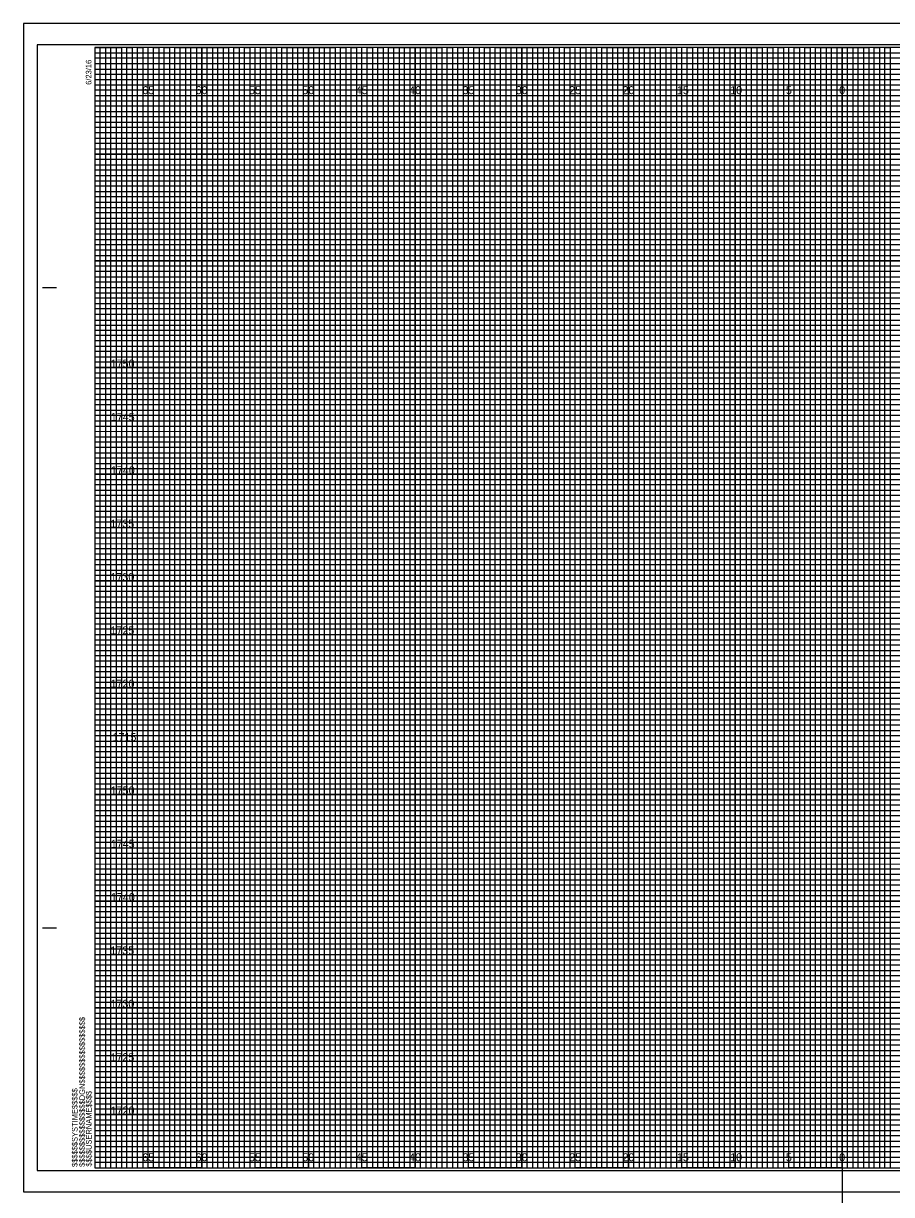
# Model space of a CAD drawing. Extents: x -7 to 162, y -2 to 327.
# Drawn here: x -6.7 to 74.6, y 107.5 to 217.2 of the extents above; entities that cross this region are included whole.
import ezdxf

# ---------------------------------------------------------------- set-up
doc = ezdxf.new("R2010")
doc.units = 0
for name, color, linetype in [('Prop XS Elevation Labels', 7, 'Continuous'), ('Prop XS Offset Labels', 7, 'Continuous'), ('Scratch_Level_5', 7, 'Continuous'), ('Sheet Cross Section CELL', 7, 'Continuous'), ('Sheet Cross Section Grid Major CELL', 7, 'Continuous'), ('Sheet Cross Section Grid Middle CELL', 7, 'Continuous'), ('Sheet Cross Section Grid Minor 1 CELL', 7, 'Continuous'), ('Sheet Cross Section Grid Minor 2 CELL', 7, 'Continuous'), ('Sheet Cutting Line CELL', 7, 'Continuous'), ('Sheet DOT Grid CELL', 7, 'Continuous'), ('Sheet Plot Border Inside CELL', 7, 'Continuous'), ('Sheet Plot Border Outside CELL', 7, 'Continuous')]:
    doc.layers.add(name, color=color, linetype=linetype)

msp = doc.modelspace()

# ---------------------------------------------------------------- linework, layer by layer
at = {"layer": 'Scratch_Level_5'}
msp.add_line((70, 176.62), (70, 106.52), dxfattribs=at)
at = {"layer": 'Sheet Cross Section CELL'}
for p, q in [((-4.9, 192.5), (-3.65, 192.5)), ((-4.85, 192.5), (-3.6, 192.5)), ((-4.9, 132.5), (-3.65, 132.5)), ((-4.85, 132.5), (-3.6, 132.5)), ((0, 110), (0, 110)), ((0, 110), (0, 110)), ((0, 110), (0, 110)), ((0, 110), (0, 110)), ((0, 110), (0, 110)), ((0, 110), (0, 110)), ((0, 110), (0, 110))]:
    msp.add_line(p, q, dxfattribs=at)
msp.add_lwpolyline([(160, 215), (0, 215), (0, 110), (160, 110)], close=True, dxfattribs=at)
at = {"layer": 'Sheet Cross Section Grid Major CELL'}
for p, q in [((5, 215), (0, 215)), ((5, 110), (5, 215)), ((15, 215), (10, 215)), ((10, 215), (10, 110)), ((15, 110), (15, 215)), ((25, 215), (20, 215)), ((20, 215), (20, 110)), ((25, 110), (25, 215)), ((35, 215), (30, 215)), ((30, 215), (30, 110)), ((35, 110), (35, 215)), ((45, 215), (40, 215)), ((40, 215), (40, 110)), ((45, 110), (45, 215)), ((55, 215), (50, 215)), ((50, 215), (50, 110)), ((55, 110), (55, 215)), ((65, 215), (60, 215)), ((60, 215), (60, 110)), ((65, 110), (65, 215)), ((75, 215), (70, 215)), ((70, 215), (70, 110)), ((10, 110), (5, 110)), ((20, 110), (15, 110)), ((30, 110), (25, 110)), ((40, 110), (35, 110)), ((50, 110), (45, 110)), ((60, 110), (55, 110)), ((70, 110), (65, 110))]:
    msp.add_line(p, q, dxfattribs=at)
for points in [[(0, 210), (160, 210), (160, 205), (0, 205)], [(0, 200), (160, 200), (160, 195), (0, 195)], [(0, 190), (160, 190), (160, 185), (0, 185)], [(0, 180), (160, 180), (160, 175), (0, 175)], [(0, 170), (160, 170), (160, 165), (0, 165)], [(0, 160), (160, 160), (160, 155), (0, 155)], [(0, 150), (160, 150), (160, 145), (0, 145)], [(0, 140), (160, 140), (160, 135), (0, 135)], [(0, 130), (160, 130), (160, 125), (0, 125)], [(0, 120), (160, 120), (160, 115), (0, 115)]]:
    msp.add_lwpolyline(points, dxfattribs=at)
at = {"layer": 'Sheet Cross Section Grid Middle CELL'}
for points in [[(0, 215), (2.5, 215), (2.5, 110), (7.5, 110), (7.5, 215), (12.5, 215), (12.5, 110), (17.5, 110), (17.5, 215), (22.5, 215), (22.5, 110), (27.5, 110), (27.5, 215), (32.5, 215), (32.5, 110), (37.5, 110), (37.5, 215), (42.5, 215), (42.5, 110), (47.5, 110), (47.5, 215), (52.5, 215), (52.5, 110), (57.5, 110), (57.5, 215), (62.5, 215), (62.5, 110), (67.5, 110), (67.5, 215), (72.5, 215), (72.5, 110), (77.5, 110)], [(0, 212.5), (137.5, 212.5)], [(0, 202.5), (160, 202.5), (160, 207.5), (0, 207.5)], [(0, 192.5), (160, 192.5), (160, 197.5), (0, 197.5)], [(0, 182.5), (160, 182.5), (160, 187.5), (0, 187.5)], [(0, 172.5), (160, 172.5), (160, 177.5), (0, 177.5)], [(0, 162.5), (160, 162.5), (160, 167.5), (0, 167.5)], [(0, 152.5), (160, 152.5), (160, 157.5), (0, 157.5)], [(0, 142.5), (160, 142.5), (160, 147.5), (0, 147.5)], [(0, 132.5), (160, 132.5), (160, 137.5), (0, 137.5)], [(0, 122.5), (160, 122.5), (160, 127.5), (0, 127.5)], [(0, 112.5), (160, 112.5), (160, 117.5), (0, 117.5)]]:
    msp.add_lwpolyline(points, dxfattribs=at)
at = {"layer": 'Sheet Cross Section Grid Minor 1 CELL'}
for p, q in [((0, 214.5), (130, 214.5)), ((130, 213.99), (0, 213.99)), ((0, 213.99), (0, 213.5)), ((0, 213.5), (130, 213.5)), ((130, 212.94), (0, 212.94)), ((0, 212.94), (0, 212)), ((0, 212), (160, 212))]:
    msp.add_line(p, q, dxfattribs=at)
for points in [[(0, 211.5), (135, 211.5), (160, 211.5), (160, 211), (0, 211)], [(0, 210.5), (160, 210.5), (160, 209.5), (0, 209.5)], [(0, 209), (160, 209), (160, 208.5), (0, 208.49)], [(0, 208), (160, 208), (160, 207), (0, 207)], [(0, 206.5), (160, 206.5), (160, 206), (0, 206)], [(0, 205.5), (160, 205.5), (160, 204.5), (0, 204.5)], [(0, 204), (160, 204), (160, 203.5), (0, 203.5)], [(0, 203), (160, 203), (160, 202), (0, 202)], [(0, 201.5), (160, 201.5), (160, 201), (0, 201)], [(0, 200.5), (160, 200.5), (160, 199.5), (0, 199.5)], [(0, 199), (160, 199), (160, 198.5), (0, 198.5)], [(0, 198), (160, 198), (160, 196.97), (160, 196.5), (160, 196), (0, 196)], [(0, 197), (160, 197), (160, 196.5), (0, 196.5)], [(0, 195.5), (160, 195.5), (160, 194.5), (0, 194.52)], [(0, 194.52), (160, 194.5), (160, 194), (0, 194)], [(0, 193.5), (160, 193.5), (160, 193), (0, 193)], [(0, 192), (160, 192), (160, 191.5), (0, 191.5)], [(0, 191), (160, 191), (160, 190.5), (0, 190.5)], [(-0.04, 189.44), (160, 189.44), (160, 188.94), (-0.04, 188.94)], [(0, 188.5), (160, 188.5), (160, 188), (0, 188)], [(0, 187), (160, 187), (160, 186.5), (0, 186.5)], [(0, 186), (160, 186), (160, 185.5), (0, 185.5)], [(0, 184.5), (160, 184.5), (160, 184), (0, 184)], [(0, 183.5), (160, 183.5), (160, 183), (0, 183)], [(0, 182), (160, 182), (160, 181.5), (0, 181.5)], [(0, 181), (160, 181), (160, 180.5), (0, 180.5)], [(0, 179.5), (160, 179.5), (160, 178.99), (0, 179)], [(0, 178.5), (160, 178.5), (160, 178), (0, 178)], [(0, 177), (160, 177), (160, 176.5), (0, 176.5)], [(0, 176), (160, 176), (160, 175.5), (0, 175.5)], [(0, 174.5), (160, 174.5), (160, 174), (0, 174)], [(0, 173.5), (160, 173.5), (160, 173), (0, 173)], [(0, 172), (160, 172), (160, 171.5), (0, 171.5)], [(0, 171), (160, 171), (160, 170.5), (0, 170.5)], [(0, 169.5), (160, 169.5), (160, 169), (0, 169)], [(0, 168.5), (160.03, 168.46), (160, 168), (0, 168)], [(0, 167), (160, 167), (160, 166.5), (0, 166.5)], [(0, 166), (160, 166), (160, 165.5), (0, 165.5)], [(0, 164.5), (160, 164.5), (160, 164), (0, 164)], [(0, 163.5), (160, 163.5), (160, 163), (0, 163)], [(0, 162), (160, 162), (160, 161.5), (0, 161.5)], [(0, 161), (160, 161), (160, 160.5), (0, 160.5)], [(0, 159.5), (160, 159.5), (160, 159), (0, 159)], [(0, 158.5), (160, 158.5), (160, 158), (0, 158)], [(0, 157), (160, 157), (160, 156.5), (0, 156.5)], [(0, 156), (160, 156), (160, 155.5), (0, 155.5)], [(0, 154.5), (160, 154.5), (160, 154), (0, 154)], [(0, 153.5), (160, 153.5), (160, 153), (0, 153)], [(0, 152), (160, 152), (160, 151.5), (0, 151.5)], [(0, 151), (160, 151), (160, 150.5), (0, 150.5)], [(0, 149.5), (160, 149.5), (160, 148.99), (0, 149)], [(0, 148.5), (160, 148.5), (160, 148), (0, 148)], [(0, 147), (160, 147), (160, 146.5), (0, 146.5)], [(0, 146), (160, 146), (160, 145.5), (0, 145.5)], [(0, 144.5), (160, 144.5), (160, 144), (0, 144)], [(0, 143.5), (160, 143.5), (160, 143), (0, 143)], [(0, 142), (160, 142), (160, 141.5), (0, 141.5)], [(0, 141), (160, 141), (160, 140.5), (0, 140.5)], [(0, 139.5), (160, 139.5), (160, 139), (0, 139)], [(0, 138.5), (160.03, 138.46), (160, 138), (0, 138)], [(0, 137), (160, 137), (160, 136.5), (0, 136.5)], [(0, 136), (160, 136), (160, 135.5), (0, 135.5)], [(0, 134.5), (160, 134.5), (160, 134), (0, 134)], [(0, 133.5), (160, 133.5), (160, 133), (0, 133)], [(0, 132), (160, 132), (160, 131.5), (0, 131.5)], [(0, 131), (160, 131), (160, 130.5), (0, 130.5)], [(0, 129.5), (160, 129.5), (160, 129), (0, 129)], [(0, 128.5), (160, 128.5), (160, 128), (0, 128)], [(0, 127), (160, 127), (160, 126.5), (0, 126.5)], [(0, 126), (160, 126), (160, 125.5), (0, 125.5)], [(0, 124.5), (160, 124.5), (160, 124), (0, 124)], [(0, 123.5), (160, 123.5), (160, 123), (0, 123)], [(0, 122), (160, 122), (160, 121.5), (0, 121.5)], [(0, 121), (160, 121), (160, 120.5), (0, 120.5)], [(0, 119.5), (160, 119.5), (160, 119), (0, 119)], [(0, 118.5), (160, 118.5), (160, 118), (0, 118)], [(0, 117), (160, 117), (160, 116.5), (0, 116.5)], [(0, 116), (160, 116), (160, 115.5), (0, 115.5)], [(0, 114.5), (160, 114.5), (160, 114), (0, 114)], [(0, 113.5), (160, 113.5), (160, 113), (0, 113)], [(0, 112), (160, 112), (160, 111.5), (0, 111.5)], [(0, 111), (160, 111), (160, 110.5), (0, 110.5)]]:
    msp.add_lwpolyline(points, dxfattribs=at)
at = {"layer": 'Sheet Cross Section Grid Minor 2 CELL'}
for points in [[(0, 110), (0.5, 110), (0.5, 215), (1, 215), (1, 110)], [(1, 110), (1.5, 110), (1.5, 215), (2, 215), (2, 110)], [(2.5, 110), (3, 110), (3, 215), (3.5, 215), (3.5, 110)], [(3.5, 110), (4, 110), (4, 215), (4.5, 215), (4.5, 110)], [(5, 110), (5.5, 110), (5.5, 215), (6, 215), (6, 110)], [(6, 110), (6.5, 110), (6.5, 215), (7, 215), (7, 110)], [(7.5, 110), (8, 110), (8, 215), (8.5, 215), (8.5, 110)], [(8.5, 110), (9, 110), (9, 215), (9.5, 215), (9.5, 110)], [(10, 110), (10.5, 110), (10.5, 215), (11, 215), (11, 110)], [(11, 110), (11.5, 110), (11.5, 215), (12, 215), (12, 110)], [(12.5, 110), (13, 110), (13, 215), (13.5, 215), (13.5, 110)], [(13.5, 110), (14, 110), (14, 215), (14.5, 215), (14.5, 110)], [(15, 110), (15.5, 110), (15.5, 215), (16, 215), (16, 110)], [(16, 110), (16.5, 110), (16.5, 215), (17, 215), (17, 110)], [(17.5, 110), (18, 110), (18, 215), (18.5, 215), (18.5, 110)], [(18.5, 110), (19, 110), (19, 215), (19.5, 215), (19.5, 110)], [(20, 110), (20.5, 110), (20.5, 215), (21, 215), (21, 110)], [(21, 110), (21.5, 110), (21.5, 215), (22, 215), (22, 110)], [(22.5, 110), (23, 110), (23, 215), (23.5, 215), (23.5, 110)], [(23.5, 110), (24, 110), (24, 215), (24.5, 215), (24.5, 110)], [(25, 110), (25.5, 110), (25.5, 215), (26, 215), (26, 110)], [(26, 110), (26.5, 110), (26.5, 215), (27, 215), (27, 110)], [(27.5, 110), (28, 110), (28, 215), (28.5, 215), (28.5, 110)], [(28.5, 110), (29, 110), (29, 215), (29.5, 215), (29.5, 110)], [(30, 110), (30.5, 110), (30.5, 215), (31, 215), (31, 110)], [(31, 110), (31.5, 110), (31.5, 215), (32, 215), (32, 110)], [(32.5, 110), (33, 110), (33, 215), (33.5, 215), (33.5, 110)], [(33.5, 110), (34, 110), (34, 215), (34.5, 215), (34.5, 110)], [(35, 110), (35.5, 110), (35.5, 215), (36, 215), (36, 110)], [(36, 110), (36.5, 110), (36.5, 215), (37, 215), (37, 110)], [(37.5, 110), (38, 110), (38, 215), (38.5, 215), (38.5, 110)], [(38.5, 110), (39, 110), (39, 215), (39.5, 215), (39.5, 110)], [(40, 110), (40.5, 110), (40.5, 215), (41, 215), (41, 110)], [(41, 110), (41.5, 110), (41.5, 215), (42, 215), (42, 110)], [(42.5, 110), (43, 110), (43, 215), (43.5, 215), (43.5, 110)], [(43.5, 110), (44, 110), (44, 215), (44.5, 215), (44.5, 110)], [(45, 110), (45.5, 110), (45.5, 215), (46, 215), (46, 110)], [(46, 110), (46.5, 110), (46.5, 215), (47, 215), (47, 110)], [(47.5, 110), (48, 110), (48, 215), (48.5, 215), (48.5, 110)], [(48.5, 110), (49, 110), (49, 215), (49.5, 215), (49.5, 110)], [(50, 110), (50.5, 110), (50.5, 215), (51, 215), (51, 110)], [(51, 110), (51.5, 110), (51.5, 215), (52, 215), (52, 110)], [(52.5, 110), (53, 110), (53, 215), (53.5, 215), (53.5, 110)], [(53.5, 110), (54, 110), (54, 215), (54.5, 215), (54.5, 110)], [(55, 110), (55.5, 110), (55.5, 215), (56, 215), (56, 110)], [(56, 110), (56.5, 110), (56.5, 215), (57, 215), (57, 110)], [(57.5, 110), (58, 110), (58, 215), (58.5, 215), (58.5, 110)], [(58.5, 110), (59, 110), (59, 215), (59.5, 215), (59.5, 110)], [(60, 110), (60.5, 110), (60.5, 215), (61, 215), (61, 110)], [(61, 110), (61.5, 110), (61.5, 215), (62, 215), (62, 110)], [(62.5, 110), (63, 110), (63, 215), (63.5, 215), (63.5, 110)], [(63.5, 110), (64, 110), (64, 215), (64.5, 215), (64.5, 110)], [(65, 110), (65.5, 110), (65.5, 215), (66, 215), (66, 110)], [(66, 110), (66.5, 110), (66.5, 215), (67, 215), (67, 110)], [(67.5, 110), (68, 110), (68, 215), (68.5, 215), (68.5, 110)], [(68.5, 110), (69, 110), (69, 215), (69.5, 215), (69.5, 110)], [(70, 110), (70.5, 110), (70.5, 215), (71, 215), (71, 110)], [(71, 110), (71.5, 110), (71.5, 215), (72, 215), (72, 110)], [(72.5, 110), (73, 110), (73, 215), (73.5, 215), (73.5, 110)], [(73.5, 110), (74, 110), (74, 215), (74.5, 215), (74.5, 110)]]:
    msp.add_lwpolyline(points, dxfattribs=at)
at = {"layer": 'Sheet Cutting Line CELL'}
for p, q in [((161.65, 217.25), (-6.7, 217.25)), ((-6.7, 217.25), (-6.7, 107.75)), ((-6.7, 107.75), (161.65, 107.75))]:
    msp.add_line(p, q, dxfattribs=at)
at = {"layer": 'Sheet DOT Grid CELL'}
for p, q in [((5, 110), (5, 215)), ((10, 110), (10, 215)), ((15, 110), (15, 215)), ((20, 110), (20, 215)), ((25, 110), (25, 215)), ((30, 110), (30, 215)), ((35, 110), (35, 215)), ((40, 110), (40, 215)), ((45, 110), (45, 215)), ((50, 110), (50, 215)), ((55, 110), (55, 215)), ((60, 110), (60, 215)), ((65, 110), (65, 215)), ((70, 110), (70, 215)), ((0, 210), (160, 210)), ((0, 205), (160, 205)), ((0, 200), (160, 200)), ((0, 195), (160, 195)), ((0, 190), (160, 190)), ((0, 185), (160, 185)), ((0, 180), (160, 180)), ((0, 175), (160, 175)), ((0, 170), (160, 170)), ((0, 165), (160, 165)), ((0, 160), (160, 160)), ((0, 155), (160, 155)), ((0, 150), (160, 150)), ((0, 145), (160, 145)), ((0, 140), (160, 140)), ((0, 135), (160, 135)), ((0, 130), (160, 130)), ((0, 125), (160, 125)), ((0, 120), (160, 120)), ((0, 115), (160, 115))]:
    msp.add_line(p, q, dxfattribs=at)
at = {"layer": 'Sheet Plot Border Inside CELL'}
msp.add_lwpolyline([(-5.4, 109.75), (161.2, 109.75), (161.2, 215.25), (-5.4, 215.25)], close=True, dxfattribs=at)
at = {"layer": 'Sheet Plot Border Outside CELL'}
msp.add_lwpolyline([(-6.7, 107.75), (161.65, 107.75), (161.65, 217.25), (-6.7, 217.25)], close=True, dxfattribs=at)

# ---------------------------------------------------------------- texts
at = {"layer": 'Prop XS Elevation Labels'}
for s, p in [('1750', (1.48, 185)), ('1745', (1.49, 180)), ('1740', (1.5, 175)), ('1735', (1.45, 170)), ('1730', (1.46, 165)), ('1725', (1.46, 160)), ('1720', (1.47, 155)), ('1715', (1.65, 150)), ('1750', (1.48, 145)), ('1745', (1.49, 140)), ('1740', (1.5, 135)), ('1735', (1.45, 130)), ('1730', (1.46, 125)), ('1725', (1.46, 120)), ('1720', (1.47, 115))]:
    msp.add_text(s, height=0.75, dxfattribs=at).set_placement(p)
at = {"layer": 'Prop XS Offset Labels'}
for s, p in [('65', (4.44, 210.62)), ('60', (9.43, 210.62)), ('55', (14.44, 210.62)), ('50', (19.43, 210.62)), ('45', (24.44, 210.62)), ('40', (29.43, 210.62)), ('35', (34.44, 210.62)), ('30', (39.43, 210.62)), ('25', (44.44, 210.62)), ('20', (49.43, 210.62)), ('15', (54.53, 210.62)), ('10', (59.52, 210.62)), ('5', (64.74, 210.62)), ('0', (69.73, 210.62)), ('0', (69.73, 210.62)), ('65', (4.44, 110.62)), ('60', (9.43, 110.62)), ('55', (14.44, 110.62)), ('50', (19.43, 110.62)), ('45', (24.44, 110.62)), ('40', (29.43, 110.62)), ('35', (34.44, 110.62)), ('30', (39.43, 110.62)), ('25', (44.44, 110.62)), ('20', (49.43, 110.62)), ('15', (54.53, 110.62)), ('10', (59.52, 110.62)), ('5', (64.74, 110.62)), ('0', (69.73, 110.62)), ('0', (69.73, 110.62))]:
    msp.add_text(s, height=0.75, dxfattribs=at).set_placement(p)
at = {"layer": 'Sheet Cross Section CELL'}
for s, p in [('6/23/16', (-0.33, 211.5)), ('$$$$$$$$$$$$$$$$DGN$$$$$$$$$$$$$$$$', (-0.94, 110.09)), ('$$$$$$SYSTIME$$$$$', (-1.63, 110.09)), ('$$$$USERNAME$$$$', (-0.31, 110.12))]:
    msp.add_text(s, height=0.525, rotation=90, dxfattribs=at).set_placement(p)

doc.saveas('drawing.dxf')
